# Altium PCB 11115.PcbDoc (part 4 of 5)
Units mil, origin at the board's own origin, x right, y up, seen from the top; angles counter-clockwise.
Board outline 4800 x 3500.1 mil, 4 copper layers (Top Layer, Layer 2, Layer 3, Bottom Layer), stack 61.6 mil thick; 316 components, 224 nets, 954 pads, 623 vias.
Unrouted connection lines stored in the file: 268.
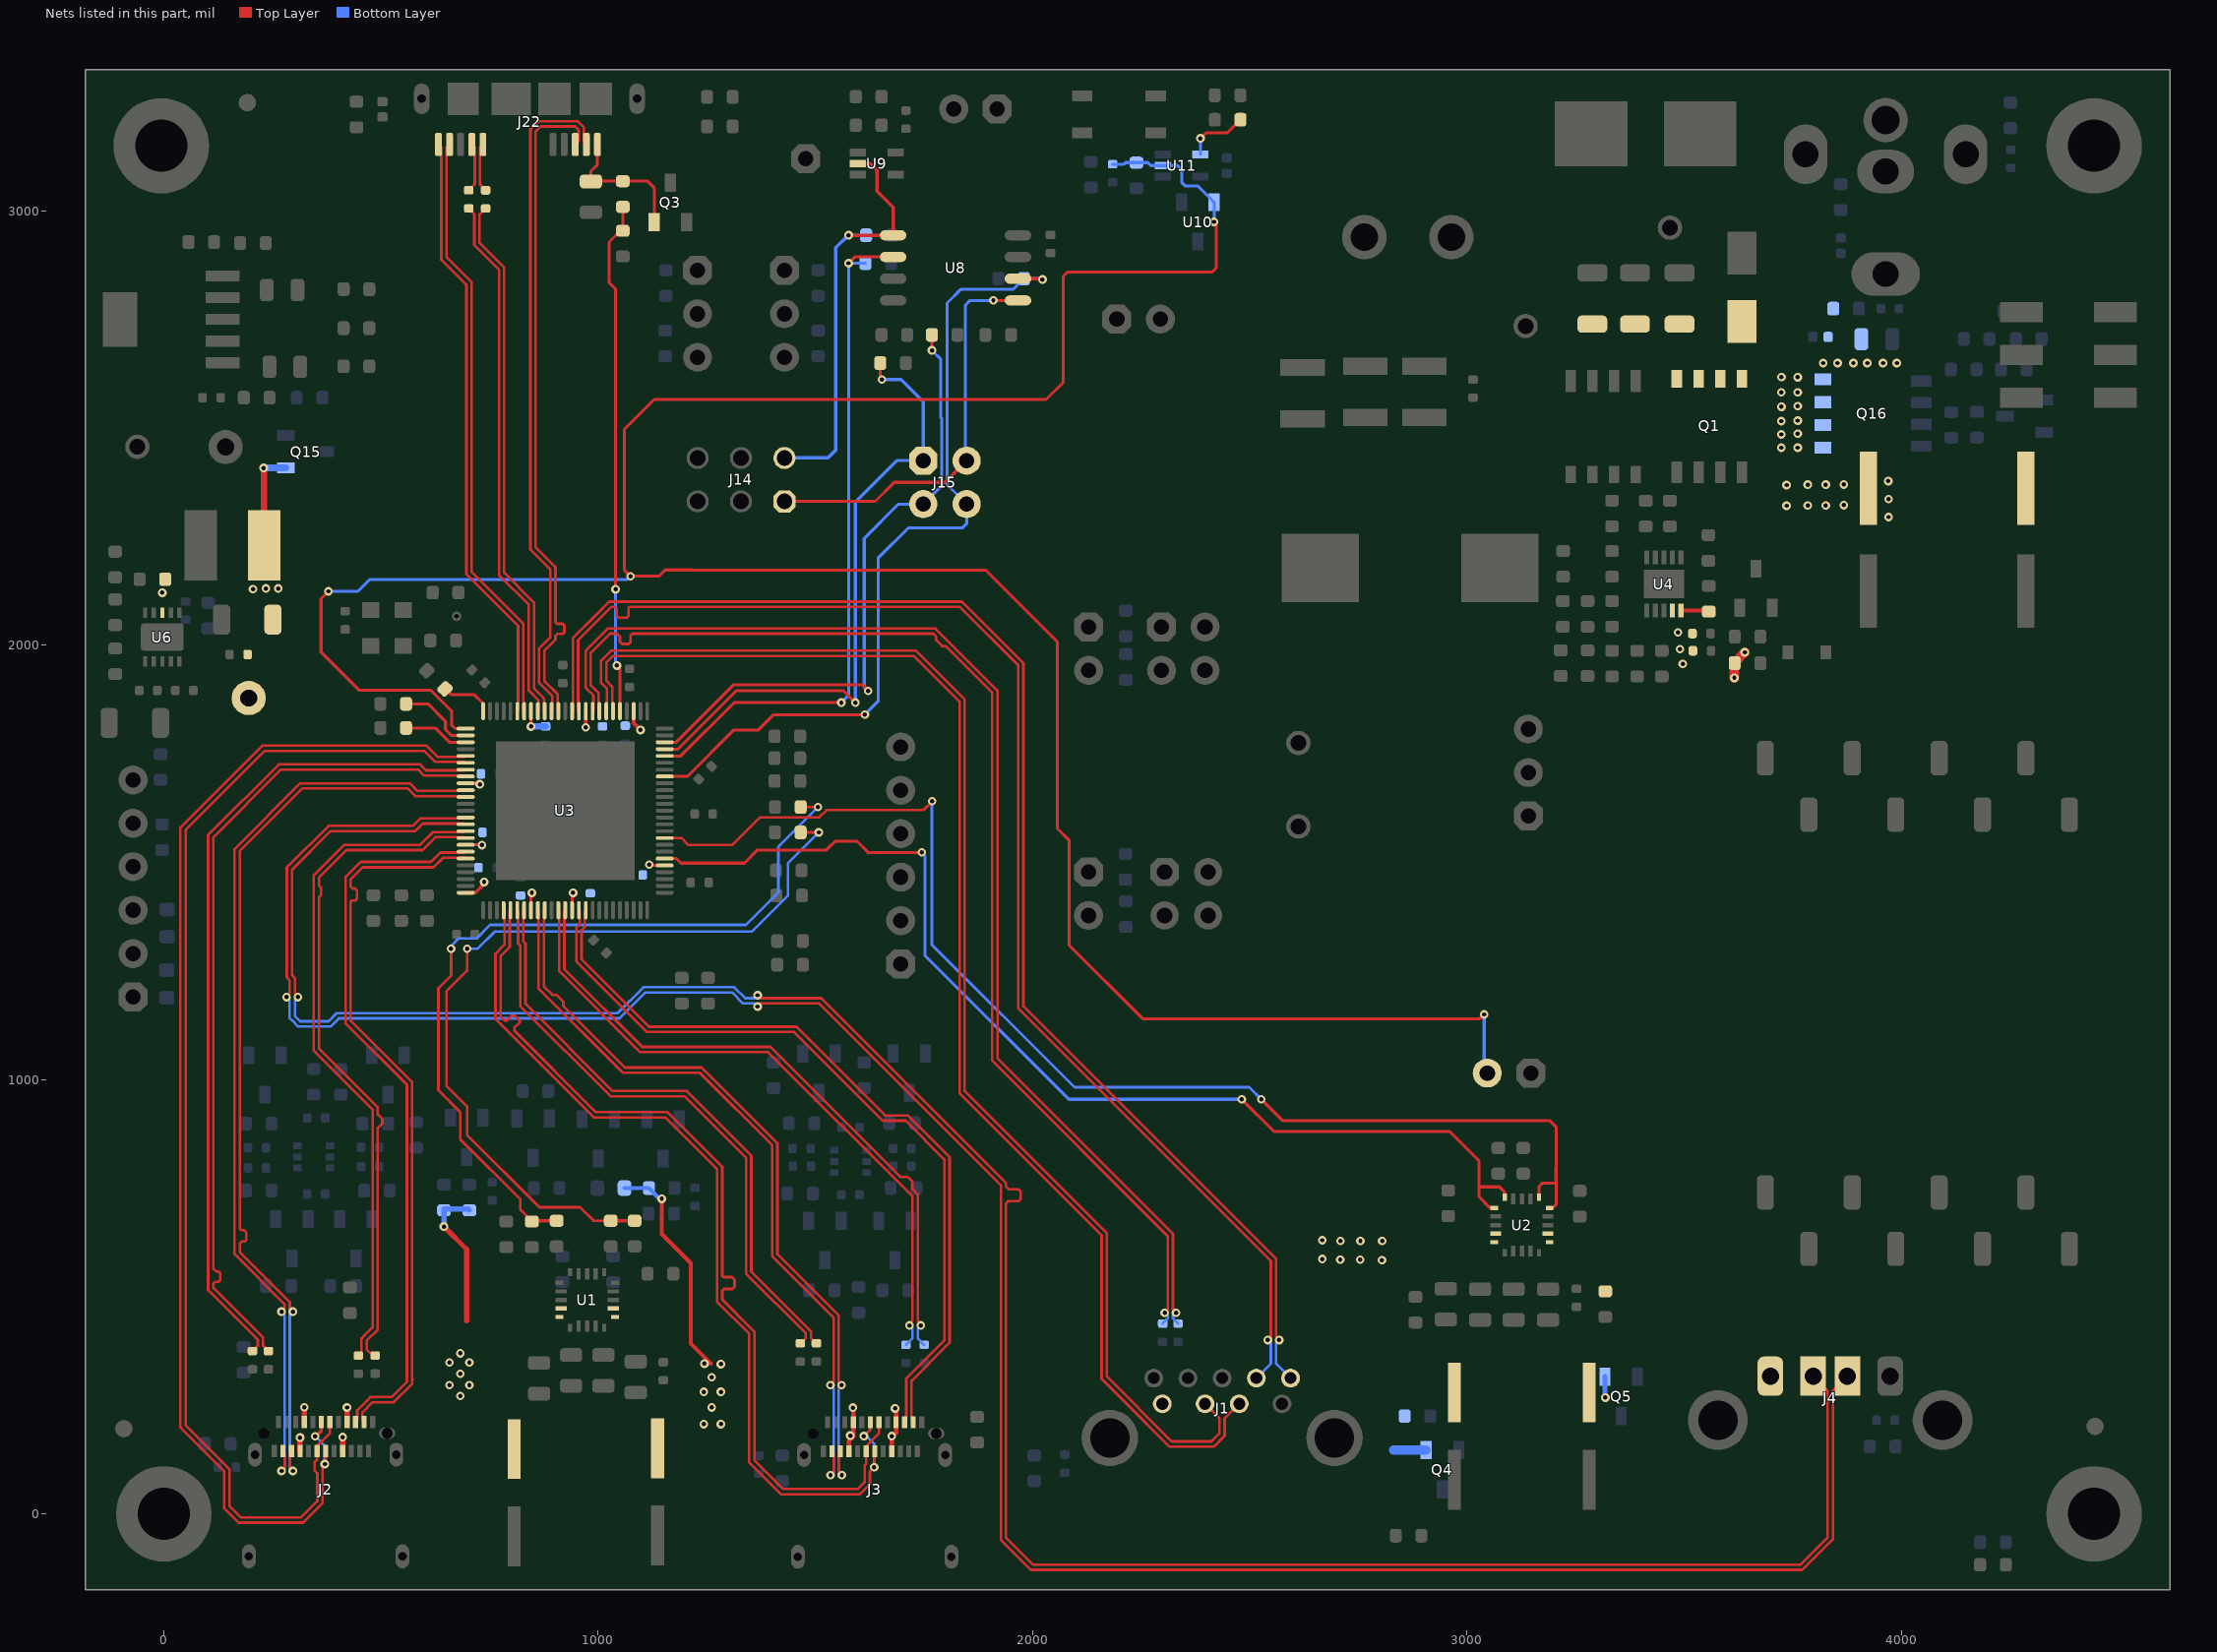
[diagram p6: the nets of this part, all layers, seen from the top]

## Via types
v1: diameter 20, hole 10, Top Layer to Bottom Layer, tented both sides, 576 vias
v2: diameter 23, hole 11, Top Layer to Bottom Layer, 36 vias
v3: diameter 20, hole 12, Top Layer to Bottom Layer, 7 vias
v4: diameter 27.56, hole 11.81, Top Layer to Bottom Layer, 4 vias

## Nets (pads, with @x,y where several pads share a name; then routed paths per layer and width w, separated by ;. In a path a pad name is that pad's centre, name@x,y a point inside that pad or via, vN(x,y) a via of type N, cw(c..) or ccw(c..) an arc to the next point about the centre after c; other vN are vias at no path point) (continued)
PF30: R30.2 U3.2 | length 178.5
  Top Layer w7: R30.2@557.83,1865 608.51,1865 648.65,1824.86 648.65,1805.68 661.96,1792.36 U3.2@695.05,1792.36
PF31: R28.2 U3.3 | length 150.9
  Top Layer w7: R28.2@557.83,1809.63 624.5,1809.63 657.51,1776.61 U3.3@695.05,1776.61
PG5V: R53.1 U4.5 | length 65
  Top Layer w10: U4.5@3493.07,2080.03 3554.54,2080.03 R53.1@3557.07,2077.51
PRT_CTL1: R7.1 R8.1 R25.1 | length 1872
  Top Layer w6: v1(661.52,1301.28) 661.52,1239.71 632.15,1210.34 632.15,975.51 682.61,925.06 682.61,862.65 820.82,724.43 820.82,700 R7.1@847.44,673.39 ; R25.1@1466.32,1627.49 v1(1506.19,1627.49)
  Top Layer w8: R7.1@847.44,673.39 848.91,674.86 R8.1@904.51,674.86
  Bottom Layer w6: v1(661.52,1301.28) 661.52,1307.61 678.91,1325 720.29,1325 751.27,1355.98 1339.99,1355.98 1414.93,1430.92 1414.93,1536.23 v1(1506.19,1627.49)
PRT_CTL2: R9.2 R10.2 R24.1 | length 1942
  Top Layer w6: v1(698.37,1301.28) 698.37,1255.7 698.07,1255.39 698.07,1250.64 650.56,1203.13 650.56,985.92 698.37,938.11 698.37,872.48 864.99,705.86 958.56,705.86 989.56,674.86 R9.2@1029.08,674.86 ; R24.1@1466.32,1569.14 v1(1508.16,1569.14)
  Top Layer w8: R9.2@1029.08,674.86 R10.2@1083.89,674.86
  Bottom Layer w6: v1(698.37,1301.28) 722.52,1301.28 761.91,1340.67 1354.1,1340.67 1436.79,1423.35 1436.79,1497.78 v1(1508.16,1569.14)
PRT_CTL3: U2.1 U2.20 U3.56 | length 2544
  Top Layer w6: 3062.11,753.02 3062.67,753.58 3063.23,753.02
  Top Layer w7: U3.56@1153.32,1508.9 1179.97,1508.9 1190.64,1498.23 1336.75,1498.23 1367.07,1528.55 1525.59,1528.55 1545.56,1548.52 1596.04,1548.52 1621.53,1523.03 v1(1744.91,1523.03) ; v1(2481.65,954.65) 2555.98,880.31 2960.71,880.31 3028.02,813.01 3028.02,753.02 ; 3062.11,753.02 3028.02,753.02 ; U2.1@3062.67,704.37 3053.61,704.37 3028.02,729.96 3028.02,753.02 ; 3063.23,753.02 3075.05,753.02 3087.28,740.79 U2.20@3087.28,728.98
  Bottom Layer w7: v1(1744.91,1523.03) 1752.25,1515.7 1752.25,1286.09 2083.68,954.65 v1(2481.65,954.65)
PRT_CTL4: U2.15 U2.16 U3.59 | length 2869.9
  Top Layer w6: U3.59@1153.32,1556.14 1191.68,1556.14 1207.82,1540 1308.9,1540 1372.64,1603.74 1509.31,1603.74 1526.03,1620.46 1748.52,1620.46 v1(1769.05,1640.99)
  Top Layer w7: v1(2526.65,954.65) 2575.56,905.73 3190.62,905.73 3205.39,890.97 3205.39,798.2 3205.16,797.97 3205.16,760.83 ; U2.16@3166.02,728.98 3166.02,753.58 3173.49,761.05 3204.94,761.05 3205.39,760.6 3205.39,712.25 3197.51,704.37 U2.15@3190.62,704.37
  Bottom Layer w7: v1(1769.05,1640.99) 1768.11,1640.05 1768.11,1310.79 2096.65,982.25 2499.05,982.25 v1(2526.65,954.65)
RBIAS: R31.2 U3.100 | length 115.7
  Top Layer w7: R31.2@650.27,1897.76 662.2,1885.83 715.18,1885.83 735.21,1865.8 U3.100@735.21,1848.27
RST: R60.1 U11.4 | length 146.8
  Top Layer w7: v1(2386.67,3167.01) 2399.62,3179.95 2448.63,3179.95 R60.1@2478.68,3210
  Bottom Layer w7: U11.4@2386.67,3130 v1(2386.67,3167.01)
RST_N: C101.2 J6.2 R120.1 U3.1 U10.2 U11.2 | length 6663.8
  Top Layer w7: v1(379.19,2124.18) 362,2107 362,1984.2 450.15,1896.05 615.04,1896.05 662.37,1848.72 662.37,1816.5 670.76,1808.11 U3.1@695.05,1808.11 ; v1(2417.51,2974.72) 2422.89,2969.34 2422.89,2868.79 2413.84,2859.73 2081.04,2859.73 2070.61,2849.3 2070.61,2605.17 2031.26,2565.82 1129.17,2565.82 1060.06,2496.71 1060.06,2173.29 v1(1074.51,2158.84) 1139.75,2158.84 1154.31,2173.4 1216.03,2173.4 1216.93,2172.49 1892.92,2172.49 2057.06,2008.35 2057.06,1578.3 2084.15,1551.21 2084.15,1309.83 2253.98,1140 3029.8,1140 v1(3039.8,1150)
  Bottom Layer w7: v1(379.19,2124.18) 446.63,2124.18 473.82,2151.38 1067.05,2151.38 v1(1074.51,2158.84) ; C101.2@2184.47,3107.56 2210.65,3107.56 2214.35,3111.25 R120.1@2239.15,3111.25 2265.66,3111.25 2272.5,3104.41 U11.2@2300.06,3104.41 2333.53,3104.41 2343.37,3094.58 2343.37,3065.98 2352.18,3057.17 2381,3057.17 U10.2@2418.17,3020 2418.17,2975.38 v1(2417.51,2974.72) ; v1(3039.8,1150) 3039.8,1022.22 J6.2@3047.02,1015
SPI_CE/PF20: J14.4 R118.1 U8.1 U9.2 | length 990.7
  Top Layer w8: v1(1576.65,2943.98) U8.1@1679.05,2943.98 1679.05,3008.28 1641.65,3045.69 1641.65,3093.88 1626.39,3109.13 U9.2@1598.34,3109.13
  Bottom Layer w8: J14.4@1428.96,2431.29 1429.06,2431.39 1529.25,2431.39 1547,2449.15 1547,2915.09 1575.9,2943.98 v1(1576.65,2943.98) R118.1@1616.95,2943.98
SPI_CLK/PF21: J15.4 R115.2 U3.68 U8.6 | length 1957.3
  Top Layer w7: U3.68@1153.32,1697.87 1153.65,1698.21 1179.74,1698.21 1205.58,1698.23 1312.35,1805 1369.15,1805 1404.34,1840.2 v1(1613.99,1840.2) ; U8.6@1966.45,2843.98 2021.09,2843.98 v1(2023.09,2841.98)
  Bottom Layer w7: v1(1613.99,1840.2) 1644.64,1870.85 1644.64,2200.83 1713.81,2270 1838.12,2270 1849,2280.88 1848.52,2281.37 J15.4@1848.52,2325 1803.61,2369.91 1803.61,2787.95 1834.84,2819.18 1955.3,2819.18 R115.2@1980.11,2843.98 2021.09,2843.98 v1(2023.09,2841.98)
SPI_D2/PF24: J15.1 R49.2 U3.72 | length 1455.4
  Top Layer w7: U3.72@1153.32,1760.87 1183.76,1760.87 1318.54,1895.65 1564.4,1895.65 v1(1592.28,1867.77) ; R49.2@1649.52,2649.73 1649.52,2615.82 v1(1653.49,2611.85)
  Bottom Layer w7: v1(1592.28,1867.77) 1592.28,2329.76 1687.52,2425 J15.1@1748.52,2425 1748.52,2560.61 1697.27,2611.85 v1(1653.49,2611.85)
SPI_D3/PF25: J15.3 R51.2 U3.73 | length 1461.2
  Top Layer w7: U3.73@1153.32,1776.61 1179.53,1776.61 1311.56,1908.65 1609.83,1908.65 v1@1616.79,1901.69 ; v1(1768.44,2678.98) R51.2@1768.44,2714.67
  Bottom Layer w7: v1(1621.53,1894.61) 1612.48,1903.66 1612.48,2246.06 1691.42,2325 J15.3@1748.52,2325 1790.52,2367 1790.52,2522.88 1789.15,2524.24 1789.15,2658.28 v1(1768.44,2678.98)
SPI_MISO/PF23: R117.2 U3.71 U8.2 | length 1623
  Top Layer w7: U3.71@1153.32,1745.12 1190.22,1745.12 1312.87,1867.77 v1(1559.89,1867.77) ; v1(1576.65,2879.73) 1590.9,2893.98 U8.2@1679.05,2893.98
  Bottom Layer w7: v1(1559.89,1867.77) 1576.65,1884.53 v1(1576.65,2879.73) R117.2@1615.11,2879.73
SPI_MOSI/PF22: J14.1 J15.2 U8.5 | length 950.8
  Top Layer w7: J14.1@1428.96,2331.29 1638.03,2331.29 1681.74,2375 1798.52,2375 J15.2@1848.52,2425 ; v1(1909.92,2793.98) U8.5@1966.45,2793.98 1971.58,2793.98 U8.5@1973.41,2792.15
  Bottom Layer w7: J15.2@1848.52,2425 1845.61,2427.91 1845.61,2783.22 1856.37,2793.98 v1(1909.92,2793.98)
UP_N: C57.1 J22.7 | length 113.9
  Top Layer w6: C57.1@702,3047.65 715.9,3061.54 715.9,3146.22 J22.7@709.1,3153.02
UP_P: C58.1 J22.6 | length 113.7
  Top Layer w6: J22.6@734.69,3153.02 727.9,3146.22 727.9,3060.61 C58.1@741,3047.51
USB2DN1/PRT_DIS_1_N: J2.A7 J2.B7 U3.6 | length 2758.4
  Top Layer w6: J2.A7@382.49,211.58 382.49,185.83 352.96,156.3 J2.B7@352.96,144.65 352.96,125.14 347,119.18 347,100.29 353.65,93.64 353.65,29.73 315.91,-8 177.38,-8 151.15,18.23 151.15,103.15 130.94,123.36 50.23,204.07 50.23,1574.97 232.13,1756.87 599.57,1756.87 625.19,1731.24 693.17,1731.24 U3.6@695.05,1729.37
USB2DN1/PRT_DIS_1_P: J2.A6 J2.B6 U3.5 | length 2877.7
  Top Layer w6: v1(348.52,178.73) 362.8,193.01 ; 357.08,184.17 362.8,189.89 362.8,193.01 ; J2.A6@362.8,211.58 362.8,193.01 ; v1@362.89,111.73 v1@365.89,114.73 ; J2.B6@372.65,144.65 372.65,121.49 v1@365.89,114.73 ; U3.5@695.05,1745.12 693.17,1743.24 630.16,1743.24 604.54,1768.87 227.16,1768.87 38.23,1579.94 38.23,199.1 46.96,190.36 139.15,98.17 139.15,13.26 172.41,-20 320.88,-20 365.65,24.76 365.65,109.73 v1(370.65,114.73) v1@365.89,114.73
  Bottom Layer w6: v1(348.52,178.73) 370.65,156.61 v1(370.65,114.73) v1@365.65,109.73
USB2DN2/PRT_DIS_2_N: J3.A7 J3.B7 U3.30 | length 2139.1
  Top Layer w6: U3.30@798.2,1390 796.32,1388.13 796.32,1305.52 775.64,1284.83 775.64,1144.52 783.89,1136.26 790.32,1136.26 801.06,1147 808.26,1147 819,1136.26 819,1131 807,1119 807,1113.16 995.1,925.06 1159.65,925.06 1285.65,799.07 1285.65,547.96 1288.59,545.02 1308.12,545.02 1314,539.15 1314,523 1309,518 1290,518 1285.65,513.65 1285.65,493.56 1359.61,419.6 1359.61,123.5 1425.93,57.18 1597.59,57.18 1613.65,73.23 1613.65,111.23 1616.65,114.23 1616.65,115.1 1616.96,115.42 J3.B7@1616.96,144 1616.96,155.32 1646.49,184.84 J3.A7@1646.49,210.93
USB2DN2/PRT_DIS_2_P: J3.A6 J3.B6 U3.29 | length 2140.6
  Top Layer w6: U3.29@782.45,1390 784.32,1388.13 784.32,1310.49 763.64,1289.8 763.64,1139.55 990.13,913.06 1154.68,913.06 1273.65,794.1 1273.65,488.59 1347.61,414.63 1347.61,118.53 1420.96,45.18 1602.56,45.18 1606.08,48.7 1625.65,68.26 1625.65,97.23 v1(1635.65,107.23) 1636.65,108.23 J3.B6@1636.65,144 ; v1(1611.65,179.08) 1626.8,194.23 J3.A6@1626.8,210.93
  Bottom Layer w6: v1(1611.65,179.08) 1617.21,179.08 1635.65,160.64 v1(1635.65,107.23)
USB2DN3/PRT_DIS_3_N: J1.2 U3.82 | length 3121.3
  Top Layer w6: U3.82@1018.67,1848.27 1020.54,1850.14 1020.54,1899.73 1006.67,1913.6 1006.67,1964.45 1029.68,1987.46 1731.82,1987.46 1844,1875.29 1844,973.21 1964.15,853.06 2171.15,646.06 2171.15,316.16 2320.49,166.82 2412.17,166.82 2430.13,184.78 2430.13,220.62 J1.2@2397.28,253.47
USB2DN3/PRT_DIS_3_P: J1.3 U3.81 | length 3121.7
  Top Layer w6: U3.81@1034.42,1848.27 1032.54,1850.14 1032.54,1904.7 1018.67,1918.57 1018.67,1959.48 1034.65,1975.46 1726.85,1975.46 1832,1870.32 1832,968.24 2159.15,641.09 2159.15,311.19 2214.65,255.7 2315.52,154.82 2417.14,154.82 2442.13,179.81 2442.13,219.59 J1.3@2476.02,253.47
USB2DN4/PRT_DIS_4_N: J4.2 U3.15 | length 5857.2
  Top Layer w6: v1(308.94,1190) 301.94,1197 301.94,1233.62 295.2,1240.36 295.2,1483.19 384.16,1572.14 578.76,1572.14 587.61,1580.99 596.13,1589.51 693.17,1589.51 U3.15@695.05,1587.64 ; v1(1367.07,1194.21) 1374.07,1187.21 1513.8,1187.21 1896.15,804.85 1939.15,761.85 1939.15,753.85 1946,747 1968,747 1973,742 1973,725 1968,720 1944,720 1939.15,715.15 1939.15,-55 2001.15,-117 3767.22,-117 3830.65,-53.57 3830.65,283.61 J4.2@3797.28,316.98
  Bottom Layer w6: v1(308.94,1190) 301.94,1183 301.94,1146.33 314.31,1133.96 379.32,1133.96 398.18,1152.82 1044.54,1152.82 1104.28,1212.57 1313.17,1212.57 1338.53,1187.21 1360.07,1187.21 v1(1367.07,1194.21)
USB2DN4/PRT_DIS_4_P: J4.3 U3.14 | length 5859.9
  Top Layer w6: v1@275,1190 v1(282.94,1190) ; v1@289.94,1197 289.94,1228.65 283.2,1235.39 283.2,1488.16 379.19,1584.14 573.79,1584.14 591.16,1601.51 693.17,1601.51 U3.14@695.05,1603.39 ; v1(1367.07,1168.21) 1374.07,1175.21 1508.83,1175.21 1927.15,756.88 1927.15,-59.97 1996.18,-129 3772.19,-129 3802.67,-98.52 3842.65,-58.54 3842.65,283.61 J4.3@3876.02,316.98
  Bottom Layer w6: v1(282.94,1190) 289.94,1183 289.94,1141.36 295.26,1136.03 309.34,1121.96 384.29,1121.96 403.16,1140.82 1049.51,1140.82 1109.25,1200.57 1308.2,1200.57 1333.56,1175.21 1360.07,1175.21 v1(1367.07,1168.21)
USB2UP_N: J22.2 U3.90 | length 1565.5
  Top Layer w6: U3.90@892.69,1848.27 894.56,1850.14 894.56,1882.97 864.23,1913.29 864.23,1992.56 889.66,2017.99 889.66,2174.99 844.15,2220.5 844.15,3187.84 861.6,3205.29 862.99,3206.68 952.42,3206.68 967,3192.1 967,3158.9 J22.2@972.88,3153.02 J22.2@972.88,3148.02
USB2UP_P: J22.3 U3.89 | length 1566
  Top Layer w6: U3.89@908.43,1848.27 906.56,1850.14 906.56,1887.94 876.23,1918.26 876.23,1987.59 901.66,2013.02 901.66,2021.5 906.68,2026.52 919.06,2026.52 922.31,2029.77 922.31,2045.68 918.59,2049.4 905.6,2049.4 901.66,2053.34 901.66,2179.96 856.15,2225.47 856.15,3182.87 867.96,3194.68 947.45,3194.68 955,3187.13 955,3160.72 J22.3@947.29,3153.02 J22.3@947.29,3148.02 ; J22.3@948.65,3146.65 J22.3@947.29,3148.02 ; J22.3@948.65,3153.02 948.65,3149.38 J22.3@947.29,3148.02
USB3DN_RX1A_N: J2.B10 U3.11 | length 2141.8
  Top Layer w6: J2.B10@293.91,144.65 290.06,140.81 290.06,105.76 v1(297.06,98.76) ; v1(297.06,465.65) 290.06,472.65 290.06,487.78 174.9,602.94 174.9,622.38 179.52,627 186,627 190,631 190,648 185,653 179,653 174.9,657.1 174.9,1526.11 318.93,1670.13 561.45,1670.13 579.08,1652.5 693.17,1652.5 U3.11@695.05,1650.63
  Bottom Layer w6: v1(297.06,98.76) 290.06,105.76 290.06,458.65 v1(297.06,465.65)
USB3DN_RX1A_P: J2.B11 U3.10 | length 2141.9
  Top Layer w6: v1(271.06,98.76) 278.06,105.76 278.06,140.81 J2.B11@274.22,144.65 ; v1(271.06,465.65) 278.06,472.65 278.06,482.81 162.9,597.97 162.9,1531.08 313.96,1682.13 566.42,1682.13 584.05,1664.5 693.17,1664.5 U3.10@695.05,1666.38
  Bottom Layer w6: v1(271.06,98.76) 278.06,105.76 278.06,458.65 v1(271.06,465.65)
USB3DN_RX1B_N: J2.A10 U3.19 | length 1691.5
  Top Layer w6: J2.A10@441.54,211.58 445.39,215.43 445.39,238.47 475.83,268.91 524.41,268.91 559.75,304.25 559.75,988.59 418.34,1130 418.34,1466.21 452.73,1500.61 452.84,1500.61 453.22,1500.99 614.95,1500.99 636.73,1522.77 693.17,1522.77 U3.19@695.05,1524.65
USB3DN_RX1B_P: J2.A11 U3.20 | length 1691.8
  Top Layer w6: J2.A11@461.23,211.58 457.39,215.43 457.39,233.5 480.8,256.91 529.38,256.91 571.75,299.28 571.75,993.56 430.34,1134.97 430.34,1409.34 433,1412 441,1412 445,1416 445,1435 440,1440 434.34,1440 430.34,1444 430.34,1461.24 457.7,1488.61 620.98,1488.61 643.15,1510.77 693.17,1510.77 U3.20@695.05,1508.9
USB3DN_RX2A_N: J3.B10 U3.35 | length 1757.1
  Top Layer w6: U3.35@876.94,1390 875.06,1388.13 875.06,1214.36 894.56,1194.86 904.45,1194.86 919.94,1179.37 919.94,1169.48 1061.66,1027.76 1238.44,1027.76 1412.81,853.39 1412.81,598.03 1554.06,456.78 v1@1554.06,289.85 ; v1@1554.06,92.85 1554.06,140.16 J3.B10@1557.91,144
  Bottom Layer w6: v1(1560.65,296.43) 1554.06,289.85 1554.06,96.27 v1(1561.06,89.27)
USB3DN_RX2A_P: J3.B11 U3.34 | length 1756.6
  Top Layer w6: U3.34@861.19,1390 863.06,1388.13 863.06,1209.39 1056.69,1015.76 1233.47,1015.76 1400.81,848.42 1400.81,593.06 1446.1,547.77 1542.06,451.81 1542.06,304.72 1541.65,304.3 1541.65,303.43 v1(1534.65,296.43) ; v1(1535.06,89.27) 1538.48,89.27 1542.06,92.85 1542.06,140.16 J3.B11@1538.22,144
  Bottom Layer w6: v1(1534.65,296.43) 1541.65,289.43 1541.65,288.56 1542.06,288.14 1542.06,96.27 v1(1535.06,89.27)
USB3DN_RX2B_N: J3.A10 U3.40 | length 1801.3
  Top Layer w6: U3.40@955.68,1390 957.55,1388.13 957.55,1356.63 949.82,1348.9 949.82,1271.87 1112.14,1109.55 1451.43,1109.55 1655.54,905.44 1707.91,905.44 1797,816.35 1797,399.23 1709.39,311.61 1709.39,225.23 1708.45,224.29 1708.45,213.84 J3.A10@1705.54,210.93
USB3DN_RX2B_P: J3.A11 U3.41 | length 1801.3
  Top Layer w6: U3.41@971.43,1390 969.55,1388.13 969.55,1351.66 961.82,1343.93 961.82,1276.84 1117.11,1121.55 1456.4,1121.55 1660.51,917.44 1712.88,917.44 1809,821.32 1809,394.26 1721.39,306.64 1721.39,225.23 1722.32,224.29 1722.32,213.84 J3.A11@1725.23,210.93
USB3DN_RX3_N: J1.5 U3.87 | length 3206.5
  Top Layer w6: U3.87@939.93,1848.27 941.8,1850.14 941.8,2016.82 997.5,2072.52 1025.23,2100.25 1837.52,2100.25 1979.15,1958.62 1979.15,1168.9 2560.76,587.29 2560.76,407.25 v1(2567.76,400.25)
  Bottom Layer w6: v1(2567.76,400.25) 2560.76,393.25 2560.76,345.9 J1.5@2594.13,312.53
USB3DN_RX3_P: J1.6 U3.86 | length 3206.4
  Top Layer w6: U3.86@955.68,1848.27 953.8,1850.14 953.8,2011.85 1030.2,2088.25 1037.75,2088.25 1043.1,2082.9 1043.1,2067.64 1047.03,2063.71 1065.93,2063.71 1070.06,2067.84 1070.06,2085.5 1072.8,2088.25 1832.55,2088.25 1967.15,1953.65 1967.15,1163.93 2548.76,582.32 2548.76,407.25 v1(2541.76,400.25)
  Bottom Layer w6: J1.6@2515.39,312.53 2548.76,345.9 2548.76,393.25 v1(2541.76,400.25)
USB3DN_TX1A_N: C10.1 U3.8 | length 1908
  Top Layer w6: C10.1@241.01,374.84 228.65,387.21 228.65,405.74 114.23,520.15 114.23,530.23 118.61,534.61 125.98,534.61 130,538.63 130,554 126.23,557.77 120.85,557.77 114.23,564.39 114.23,1557.97 269.88,1713.62 585.38,1713.62 599.26,1699.75 693.17,1699.75 U3.8@695.05,1697.87
USB3DN_TX1A_P: C9.1 U3.7 | length 1907.4
  Top Layer w6: C9.1@204.2,374.84 216.65,387.29 216.65,400.76 211.65,405.76 162.91,454.51 102.23,515.18 102.23,1562.94 264.91,1725.62 590.35,1725.62 604.23,1711.75 693.17,1711.75 U3.7@695.05,1713.62
USB3DN_TX1B_N: C11.1 U3.16 | length 1567.2
  Top Layer w6: C11.1@447.94,364.31 455,371.37 455,403.66 461.23,409.88 480.65,429.3 480.65,931.27 348.9,1063.02 345.39,1066.53 345.39,1470.04 415.74,1540.39 590.67,1540.39 620.29,1570.02 693.17,1570.02 U3.16@695.05,1571.89
USB3DN_TX1B_P: C12.1 U3.17 | length 1567.6
  Top Layer w6: C12.1@486.52,364.68 481.23,364.68 467,378.91 467,398.69 492.65,424.33 492.65,888.65 503,899 503,909.77 492.65,920.13 492.65,936.24 357.39,1071.5 357.39,1420 362,1424.61 362,1442.38 357.39,1446.99 357.39,1465.06 420.71,1528.39 595.64,1528.39 611.59,1544.34 625.26,1558.02 693.17,1558.02 U3.17@695.05,1556.14
USB3DN_TX2A_N: C15.1 U3.32 | length 1377.4
  Top Layer w6: U3.32@829.69,1390 827.82,1388.13 827.82,1318.1 832.55,1313.37 832.55,1174.71 1033.6,973.67 1203.99,973.67 1352.65,825.01 1352.65,557.77 1489.95,420.46 1489.95,405.08 C15.1@1502.38,392.65
USB3DN_TX2A_P: C14.1 U3.31 | length 1377.4
  Top Layer w6: U3.31@813.95,1390 815.82,1388.13 815.82,1313.13 820.55,1308.4 820.55,1169.74 1028.63,961.67 1199.02,961.67 1340.65,820.04 1340.65,552.8 1477.95,415.49 1477.95,405.08 C14.1@1465.53,392.65
USB3DN_TX2B_N: C67.1 U3.37 | length 1523.4
  Top Layer w6: U3.37@908.43,1390 910.31,1388.13 910.31,1249.68 1096.74,1063.25 1391.28,1063.25 1723.69,730.85 1723.69,444.41 1716.69,437.41 v1(1716.69,433.89)
  Bottom Layer w6: C67.1@1708.65,389.1 1723.69,404.14 1723.69,427.23 1717.02,433.89 v1(1716.69,433.89)
USB3DN_TX2B_P: C66.1 U3.38 | length 1523.4
  Top Layer w6: U3.38@924.18,1390 922.31,1388.13 922.31,1254.66 1101.71,1075.25 1396.25,1075.25 1695.75,775.75 1712.79,775.75 1723.69,764.86 1723.69,747.82 1735.69,735.82 1735.69,444.41 1742.69,437.41 v1(1742.69,433.89)
  Bottom Layer w6: v1@1735.69,427.23 1735.69,404.27 C66.1@1750.73,389.23
USB3DN_TX3_N: C68.1 U3.84 | length 2811.5
  Top Layer w6: U3.84@987.17,1848.27 989.05,1850.14 989.05,1884.76 974.64,1899.17 971.13,1902.68 971.13,1987.46 974.64,1990.98 1010.19,2026.52 1022.25,2038.58 1776.42,2038.58 1919.15,1895.85 1919.15,1048.98 2323.44,644.68 2323.44,470 v1(2330.44,463)
  Bottom Layer w6: v1(2330.44,463) 2323.44,456 2323.44,449.95 C68.1@2335.17,438.22
USB3DN_TX3_P: C69.1 U3.83 | length 2811.9
  Top Layer w6: U3.83@1002.92,1848.27 1001.05,1850.14 1001.05,1889.73 983.13,1907.65 983.13,1982.49 1027.22,2026.58 1043.92,2026.58 1050.17,2020.34 1050.17,2007.83 1055,2003 1070.06,2003 1074.51,2007.45 1074.51,2022.09 1079,2026.58 1771.45,2026.58 1778,2020.03 1778,2011.83 1791.82,1998.01 1800.01,1998.01 1907.15,1890.88 1907.15,1044.01 2311.44,639.71 2311.44,470 v1(2304.44,463)
  Bottom Layer w6: C69.1@2299.72,438.23 2311.44,449.95 2311.44,456 v1(2304.44,463)
USB3UP_RX_N: J22.9 U3.94 | length 1381.5
  Top Layer w6: J22.9@657.92,3153.02 651.13,3146.22 651.13,2892.87 708.68,2835.32 708.68,2168.54 827.82,2049.4 827.82,1850.14 U3.94@829.69,1848.27
USB3UP_RX_P: J22.10 U3.95 | length 1381.5
  Top Layer w6: J22.10@632.33,3153.02 639.13,3146.22 639.13,2887.9 696.68,2830.35 696.68,2163.57 815.82,2044.43 815.82,1850.14 U3.95@813.95,1848.27
USB3UP_TX_N: C57.2 U3.92 | length 1225.1
  Top Layer w6: C57.2@702,3005.91 715,2992.91 715,2921.37 771.73,2864.65 771.73,2161.81 840.23,2093.3 840.23,1895.88 863.06,1873.05 863.06,1850.14 U3.92@861.19,1848.27
USB3UP_TX_P: C58.2 U3.91 | length 1225.4
  Top Layer w6: C58.2@741,3005.78 727,2991.78 727,2926.34 783.73,2869.62 783.73,2166.78 852.23,2098.27 852.23,1900.85 875.06,1878.02 875.06,1850.14 U3.91@876.94,1848.27
VBUS1: C1.1 J2.A4 J2.A9 J2.B4 J2.B9 R76.2 R77.2 U1.4 U1.5 | length 473.5
  Top Layer w12: J2.B9@313.59,144.65 v1(313.59,175.68) v1@316.65,178.73 ; J2.A4@323.43,211.58 v1@323.43,245.07 ; J2.B4@412.02,144.65 v1(412.02,176.86) ; J2.A9@421.86,211.58 v1(421.86,244.85) ; v1(644.91,661.68) 697.38,609.21 697.38,444.13
  Bottom Layer w12: v1(644.91,661.68) R77.2@644.91,699.04 644.91,701.7 700.97,701.7 R76.2@703.65,699.02
  other v1: 323.43,245.65 682.55,271.62 657.65,296.43 703.65,296.43 682.55,322.54 657.65,348.56 703.65,348.56 682.55,369.86
VBUS2: C2.1 J3.A4 J3.A9 J3.B4 J3.B9 R80.2 R81.2 U1.11 U1.12 | length 731.2
  Top Layer w10: v1(1146.38,725.36) 1146.38,644.02 1213.22,577.18 1213.22,392.35 1259.67,345.91 ; J3.B9@1577.59,144 1577.59,168.18 1587.43,178.02 J3.A4@1587.43,210.93 v1@1587.43,244.73 ; J3.B4@1676.02,144 1676.02,176.22 1685.86,186.07 J3.A9@1685.86,210.93 1685.86,240.57 v1(1683.65,242.79) v1@1683.65,242.55
  Bottom Layer w10: R81.2@1060.69,750.16 R80.2@1116.86,750.16 1141.66,725.36 v1(1146.38,725.36)
  other v1: 1676.02,179.08 1580.65,180.23 1243.22,206.77 1282.65,206.77 1261.56,245.07 1586.65,244.73 1243.22,281.03 1282.65,281.03 1261.56,314.42 1282.65,344.85 1244.67,345.91
VBUS3: C3.1 J1.1 Q4.1 R66.2 U2.4 U2.5 | length 75.4
  Bottom Layer w22: 2831.09,147.06 Q4.1@2906.45,147.06
  other v1: 2804.59,584.22 2708.42,585.46 2754.44,585.16 2667.14,586.72 2708.92,628.39 2754.93,628.39 2805.09,628.39 2667.14,630.08
VBUS4: C4.1 J4.1 Q5.1 R4.2 U2.11 U2.12 | length 48.1
  Bottom Layer w12: Q5.1@3317.99,315.73 3317.99,268.69 v1(3318.76,267.92)
VBUS_0: C59.2 J22.1 Q3.1 R56.1 | length 318.3
  Top Layer w7: J22.1@998.47,3148.02 998.47,3106.76 983.29,3091.58 C59.2@983.29,3067.79 983.94,3068.44 R56.1@1056.65,3068.44 1114.07,3068.44 1129.24,3053.26 Q3.1@1129.17,2974.04 Q3.1@1129.17,2974.04
VBUS_DET: R54.2 R56.2 U3.80 | length 1189.9
  Top Layer w7: v1(1040.31,2128.81) 1040.31,2819.77 1025.23,2834.85 1025.23,2928.32 R54.2@1056.65,2959.73 ; v1(1043.1,1953.37) 1050.17,1946.3 U3.80@1050.17,1848.27 ; R54.2@1056.65,2954.26 R54.2@1056.65,2959.73 ; R56.2@1056.65,3009.38 R54.2@1056.65,2959.73
  Bottom Layer w7: v1(1040.31,2128.81) 1040.31,1956.16 v1(1043.1,1953.37)
VCORE: C26.2 C84.1 C85.1 C86.1 C87.1 C88.1 C89.1 C90.1 C91.1 C92.1 C97.2 L2.2 Q15.1 R112.2 TP5.1 U3.9 U3.18 U3.25 U3.33 U3.39 U3.55 U3.78 U3.85 U3.93 U6.3 | length 654.7
  Top Layer w7: U3.25@677.61,1430.16 U3.25@695.05,1430.16 ; U3.18@695.05,1540.39 732.06,1540.39 v1(732.45,1540) ; U3.9@695.05,1682.13 725.32,1682.13 v1(727.45,1680) ; U3.33@845.44,1390 845.44,1427.99 v1(847.45,1430) ; v1(845.44,1812.99) U3.93@845.44,1848.27 ; U3.39@939.93,1390 939.93,1427.48 v1(942.45,1430) ; U3.85@971.43,1848.27 971.43,1811.02 v1(971.55,1810.9) ; v1(1117.45,1495) 1119.3,1493.15 U3.55@1153.32,1493.15
  Top Layer w8: U3.25@695.05,1430.16 717.61,1430.16 737.45,1450 v1(737.45,1455)
  Top Layer w9: U3.78@1081.66,1848.27 1081.66,1820.79 v1(1097.45,1805)
  Top Layer w15: v1(229.83,2408.34) 231.06,2407.11 L2.2@231.06,2229.97
  Bottom Layer w7: v1(847.45,1430) v1@851.58,1434.13
  Bottom Layer w15: v1(229.83,2408.34) Q15.1@281.11,2408.34 ; v1(845.44,1812.99) 845.68,1813.23 C92.1@879.13,1813.23
  other v1: -3.4,2121 205.31,2129.17 235.21,2130.78 263.51,2130.78
VIN: C27.1 C29.2 C33.2 C37.2 C39.2 C40.2 C41.1 C42.1 C43.2 D4.2 Q1.5 Q1.6 Q1.7 Q1.8 Q16.5 Q16.6 Q16.7 Q16.8 R32.1 R41.2 U4.4 | length 68.6
  Top Layer w22: v1(3615.9,1925) 3615.9,1958.13 R41.2@3616.63,1958.86 3616.63,1960.43 v1(3639.86,1983.66)
  other v1: 3496.99,1957.21 3490.47,1990.87 3486.05,2029.36 3970.89,2295.12 3736.21,2321.29 3784.81,2321.96 3826.12,2321.96 3867.83,2322.64 3970.89,2336.43 3736.21,2368.9 3784.81,2369.57 3826.12,2369.57 3867.83,2370.24 3970.22,2378.13 3724.15,2454.92 3761.64,2454.92 3724.17,2485.53 3761.63,2487.21 3724.15,2516.02 3761.61,2517.21 3724.18,2549.1 3761.61,2550.57 3724.15,2582.21 3761.61,2582.21 3724.2,2617.4 3761.59,2617.12 3820.11,2649.69 3853.37,2649.69 3889.83,2649.69 3921.76,2649.69 3958.01,2649.69 3989.83,2649.69
pads on no net: D11.2 D12.2 D13.2 D14.2 FID1.1 FID2.1 FID3.1 FID4.1 FID5.1 FID6.1 J2.0 J2.A8 J2.B8 J3.0 J3.A8 J3.B8 J10.4 J13.4 J20. J22.4 U9.1 U11.1

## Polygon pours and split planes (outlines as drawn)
5V_BRD on Top Layer "Full" (solid, remove dead copper, pour order 238): -25.58,1786.49 -25.58,1901.62 -6.76,1920.44 -6.76,1976.54 21.86,1976.54 21.86,1944.45 37.76,1928.55 37.76,1876.11 48.05,1865.82 48.05,1787.46 40.94,1780.36 -18.23,1780.36 -24.37,1786.49
3V3_BRD on Top Layer "Top Layer-3V3_BRD" (solid, pour order 290): 3134.8,1235 3143.08,1243.28 3143.08,1281.72 3129.8,1295 3015.48,1295 3009.3,1288.82 3009.3,1244.54 3018.84,1235
VBUS2 on Top Layer "Full" (solid, remove dead copper, pour order 210): 1076.05,74.87 1074.6,215.82 1081.13,228.76 1183.06,228.76 1199.02,244.73 1199.02,312.58 1183.06,330.69 1183.06,371.37 1163.71,392.31 1106.34,392.31 1068.49,430.15 1044.73,430.15 1022.47,452.41 1022.47,477.84 1093.94,477.84 1121.77,505.67 1202.76,505.67 1309,380.41 1309,72.71 1296.23,60.02 1086.42,60.02
VBUS1 on Top Layer "Full" (solid, remove dead copper, pour order 208): 784.74,74.87 835.44,74.87 848.91,86.77 848.91,213.84 835.44,226.85 763.64,226.85 756.44,238.69 756.44,322.95 763.64,330.36 795.41,331.31 796.32,332.36 881.38,430.67 905.14,430.67 927.4,452.93 927.4,478.36 855.94,478.36 839.63,494.66 791.44,494.66 658.04,494.66 639.65,478.36 639.65,86.77 650.56,74.87
VBUS_0 on Top Layer "Full" (solid, remove dead copper, pour order 289): 995.44,3183 991,3178.56 991,3120 958,3087 958,3058.2 965.2,3051 1089,3051 1097,3043 1097,2948 1104,2941 1132.58,2941 1139.75,2948.17 1139.75,3162.25 1119,3183
GND on Top Layer "Full" (solid, remove dead copper, pour order 281): 3680.22,2229.04 3698.52,2210.74 3698.52,2143.93 3689.64,2135.06 3689.64,2060.92 3694.15,2056.41 3778.58,2056.41 3802.53,2032.46 3802.53,1953.55 3850.76,1905.32 4564.47,1905.32 4594.15,1935 4594.15,2205 4574,2225.15 3753.14,2225.15 3689.64,2288.65 3689.64,2328.66 3677.94,2340.36 3540.82,2340.36 3527.61,2327.15 3527.61,2232.7 3531.27,2229.04
VBUS3 on Top Layer "Full" (solid, remove dead copper, pour order 279): 2997.17,198.77 3003.4,205 3003.4,349.05 2995.22,357.23 2844.51,357.23 2836.37,365.37 2836.37,506.18 2926.15,595.96 3051.8,595.96 3079.8,623.96 3079.8,650.96 2646.8,650.96 2633.8,637.96 2633.8,251.69 2642.7,242.79 2754.42,242.79 2798.44,198.77
GND on Top Layer "Full" (solid, remove dead copper, pour order 277): 3399.15,-35 3399.15,101.79 3355.4,145.54 3248.61,145.54 3232.62,161.53 3232.62,385 3237.62,390 3338.9,390 3349.15,400.25 3349.15,455 3339.15,465 3337.15,463 3266.8,463 3259.8,470 3259.8,480 3244.8,480 3244.8,470 3237.8,463 2925.85,463 2919.8,456.94 2919.8,381.35 3009.3,381.35 3039.8,350.85 3039.8,171.72 3025.44,157.36 2937.68,157.36 2917.3,136.99 2917.3,-58.15 2939.9,-80.75 3376.95,-80.75 3399.15,-58.54
GND on Top Layer "Full" (solid, remove dead copper, pour order 275): 639.65,-130 1304.65,-130 1317.65,-117 1317.65,32.37 1304.83,45.18 1077.27,45.18 1062.44,60.02 1062.44,236.07 1071.44,245.07 1174.31,245.07 1183.71,254.47 1183.71,302.48 1171.77,314.42 787.95,314.42 781.54,308.02 781.54,252.99 788.88,245.65 845.98,245.65 870.13,221.51 870.13,53.76 861.55,45.18 651.36,45.18 639.65,33.47
VBUS4 on Top Layer "Full" (solid, remove dead copper, pour order 271): 3254.8,190 3334.15,190 3464.15,60 3694.15,60 3744.15,110 3744.15,484.69 3577.88,650.96 3173.89,650.96 3173.89,625.24 3178.42,620.71 3188.07,611.07 3201.41,611.07 3294.15,518.33 3294.15,500 3299.15,495 3349.15,495 3364.15,480 3364.15,375 3349.15,360 3254.8,360
GND on Top Layer "Full" (solid, remove dead copper, pour order 267): -68.68,1974.13 -55.22,1987.59 25.96,1987.59 31.05,1982.49 30.88,1953.57 52.7,1931.75 52.7,1883.34 57.62,1878.42 81.83,1878.42 90.32,1886.91 90.32,1961.62 99.2,1970.5 160.11,1970.5 160.11,1987.46 156.59,1990.98 156.6,2017.99 160.11,2021.5 160.11,2093.57 156.08,2097.6 102.46,2097.6 90.32,2085.46 90.32,2054.32 85.39,2049.4 -64.97,2049.4 -92.87,2021.5 -163.31,2021.5 -170.85,2013.97 -170.85,1979.13 -165.85,1974.13
GND on Top Layer "Full" (solid, remove dead copper, pour order 265): -60.85,1855 -38.51,1877.34 -38.51,1911.03 -16.84,1932.89 -16.89,1976.54 -30.85,1976.54 -30.85,1948.49 -48.69,1932.89 -60.54,1932.89 -87.47,1905.96 -150.28,1905.96 -160.85,1895.39 -160.85,1764.34 -145.97,1749.46 -73.41,1749.46 -60.85,1762.02
NetF1_2 on Top Layer "Full" (solid, remove dead copper, pour order 261): 2911.87,2875.69 2995.49,2875.69 3151.7,3031.89 3370.5,3031.89 3370.5,3260 3369.02,3260 3359.02,3270 3049.09,3270 2883.84,3104.74 2883.84,2885.17 2892.18,2876.83
5V_BRD on Top Layer "Full" (solid, remove dead copper, pour order 259): 2814.15,1978.32 2824.18,1988.35 2825.26,2281.52 3049.15,2505.41 3049.15,2563.63 3036.37,2576.41 2991.6,2576.41 2964.29,2549.1 2559.92,2549.1 2543.28,2532.46 2543.28,2004.1 2543.28,1735 2552.46,1721.69 2665.84,1721.69 2674.15,1730 2679.15,1958.86 2695.92,1975.63
GND on Top Layer "Full" (solid, remove dead copper, pour order 257): 2574.15,2611.75 3152.89,2611.75 3184.15,2643.01 3184.15,2792.87 3215.84,2824.57 3646.16,2824.57 3670.33,2848.73 3670.33,2948.99 3661.91,2957.41 3577.73,2957.41 3565.32,2945 3565.32,2916.49 3541.32,2892.5 3434.52,2892.5 3357.68,2969.34 3145.99,2969.34 3025.38,2848.74 2890.34,2848.73 2834.15,2904.92 2834.15,2973.91 2798.06,3010 2577.65,3010 2562.06,2994.41 2562.06,2620.17 2568.84,2613.4
GND on Top Layer "Full" (solid, remove dead copper, pour order 255): 50.03,2363.12 62.13,2375.22 62.13,2735 229.83,2735 238.59,2743.75 238.59,2763.13 62.98,2763.13 -16.89,2843 -140.1,2843 -153.16,2829.94 -153.16,2369.83 -146.46,2363.12
3V3_BRD on Top Layer "Full" (solid, remove dead copper, pour order 253): 94.15,2782.69 250.36,2782.69 257.67,2790 256.83,2790.84 256.83,2853.56 293.35,2886.24 293.35,2953.1 286.72,2959.73 250.36,2959.73 223.05,2959.73 215.25,2951.93 215.25,2897.8 197.59,2880.15 197.59,2823.33 192.39,2818.13 94.36,2818.13
5V_BRD on Top Layer "Full" (solid, remove dead copper, pour order 251): 94.15,2685 174.02,2685 205.31,2653.71 205.31,2604.09 210.05,2599.35 256.83,2599.35 263.51,2606.03 263.51,2689.93 239.19,2714.25 93.73,2714.25 86.48,2707 86.48,2692.67
LVCORE on Top Layer "Full" (solid, remove dead copper, pour order 249): 78.13,2063.95 78.13,2093.57 126,2141.44 126,2312.37 46.96,2312.37 46.96,2107.44 27.27,2087.75 27.27,2063.95
no net on Top Layer "Full" (solid, remove dead copper, pour order 243): -13.26,2265
VCORE on Top Layer "Full" (solid, remove dead copper, pour order 241): -10.62,2067.41 -10.62,2102.46 -20.03,2111.87 -20.03,2201.71 -16.84,2204.9 19.7,2204.9 24.51,2200.1 24.51,2134.59 3.69,2113.78 3.69,2067.15 3.16,2066.63
VCORE on Top Layer "Full" (solid, remove dead copper, pour order 239): 127.03,1919.53 132.26,1924.76 187.97,1980.47 187.97,2151.38 172.22,2167.13 172.22,2308.52 182.52,2318.82 287.9,2318.82 299.27,2307.45 299.27,1811.02 290.29,1802.05 135.39,1802.05 127.03,1809.69 127.03,1833.55 127.03,1846.47
GND on Top Layer "Full" (solid, remove dead copper, pour order 236): 3269.02,2571.38 3277.01,2571.38 3419.24,2571.38 3424.07,2571.38 3428,2577.39 3428,2671.99 3414.56,2685.43 3266.91,2685.43 3262.24,2680.75 3262.24,2578.16
L5V on Top Layer "Full" (solid, remove dead copper, pour order 232): 3169.15,2304.73 3184.15,2319.73 3353.88,2319.73 3359.15,2325 3359.15,2355.72 3370.5,2367.07 3596.22,2367.07 3604.15,2375 3604.15,2425.83 3594.98,2435 3424.15,2435 3414.33,2444.82 3414.33,2538.33 3401.3,2551.35 3170.5,2551.35 2984.15,2365 2984.15,2093.08 3167.23,2093.08 3169.15,2095
VIN on Top Layer "Full" (solid, remove dead copper, pour order 230): 3459.15,2455.33 3689.64,2455.33 3714.15,2430.83 3714.15,2295 3739.15,2270 4324.15,2270 4343.7,2289.55 4343.7,2510.45 4329.15,2525 4149.15,2525 4134.15,2540 4134.15,2735 4119.15,2750 3706.65,2750 3670.33,2786.32 3581.66,2786.32 3242.41,2786.32 3229.15,2773.07 3229.15,2702.28 3236.43,2695 3424.87,2695 3444.02,2675.85 3444.02,2466.9 3454.15,2456.77
DC_IN on Top Layer "Full" (solid, remove dead copper, pour order 228): 3453.7,3090.95 3453.7,3029.28 3424.15,2999.73 3424.15,2934.87 3444.02,2915 3515.46,2915 3533.23,2932.77 3533.23,2969.08 3544.15,2980 3679.15,2980 3694.15,2965 3694.15,2820 3744.15,2770 4069.15,2770 4104.15,2805 4104.15,2915 4074.15,2945 3849.15,2945 3714.15,3080 3714.15,3250 3694.15,3270 3464.15,3270 3454.15,3260
VIN on Top Layer "Full" (solid, remove dead copper, pour order 226): 3528.17,1950 3528.17,2042.01 3522.4,2047.77 3496.28,2047.77 3483.23,2060.82 3483.23,2093.08 3464.62,2093.08 3464.62,2009.06 3473.68,2000 3473.68,1946.47 3476.42,1943.73 3520.46,1943.73
5V_BRD on Top Layer "Full" (solid, remove dead copper, pour order 206): 895.94,330.36 913.08,347.5 1034.05,347.5 1053.22,328.33 1162.52,328.33 1166.9,332.71 1166.9,371.39 1157.43,380.86 1099.44,380.86 1062.44,417.86 1042.99,417.86 1015.39,445.45 933.89,445.45 906.52,418.08 887.66,418.08 835.44,365.86 835.44,332.36 837.44,330.36
5V_BRD on Top Layer "full" (solid, remove dead copper, pour order 150): 3054.8,509.96 3129.8,509.96 3259.8,509.96 3264.8,514.96 3264.8,529.96 3244.8,549.96 3209.8,584.96 3184.8,584.96 3174.8,594.96 3174.8,607.17 3174.09,607.88 3085.51,607.88 3063.86,586.22 2936.91,586.22 2914.8,564.11 2914.8,514.96 2919.8,509.96
VBUS2 on Bottom Layer "Full" (solid, remove dead copper, pour order 214): 1225.67,163.51 1479.7,163.51 1487.65,171.46 1487.65,327.51 1498.06,337.92 1588.96,337.92 1598.37,328.5 1598.38,305.65 1572.65,279.92 1572.65,193.68 1567.75,188.78 1567.75,161.13 1577.59,151.29 1687.88,151.29 1702.65,166.06 1702.65,319.04 1599.46,422.23 1436.27,422.24 1352.65,505.86 1242.65,505.86 1208.28,463.76 1208.28,180.9
GND on Bottom Layer "Full" (solid, remove dead copper, pour order 287): -170.85,1728.25 81.4,1728.25 102.06,1748.91 102.06,2055.74 91.02,2066.78 -167.51,2066.78 -170.85,2063.44
DC_IN on Bottom Layer "Full" (solid, remove dead copper, pour order 285): 4069.94,2490 4095.96,2516.02 4135.09,2516.02 4141.65,2522.58 4141.65,2867.5 4094.15,2915 3852.56,2915 3836.19,2898.63 3836.19,2817.96 3849.15,2805 3969.89,2805 3986.07,2788.82 3986.07,2750.83 3964.15,2728.91 3964.15,2685.21 3970.89,2678.47 4013.8,2678.47 4019.15,2673.11 4019.15,2622.4 4014.15,2617.4 4014.15,2490
VBUS3 on Bottom Layer "Full" (solid, remove dead copper, pour order 273): 2244.15,276.47 2367.06,276.47 2449.15,276.47 2644.15,276.47 2656.48,288.8 2656.48,529.65 2634.48,551.65 2633.8,639.71 2644.15,650.96 2674.15,650.96 2857.9,650.96 2869.15,639.71 2869.15,538.96 2869.15,316.98 2869.15,93.98 2869.15,-15 2849.15,-45 2285.19,-45 2231.62,2.18 2231.62,219.31 2231.62,263.94
VCORE on Bottom Layer "Full" (solid, remove dead copper, pour order 245): 1123.28,1392.71 1141.47,1410.9 1141.47,1515.79 1136.18,1523.03 1104.23,1523.03 1060.8,1470.96 965.12,1472.14 768.25,1470.96 747.56,1472.14 745.26,1663.84 745.26,1776.61 761.95,1793.3 782.31,1793.3 869.95,1793.3 994.39,1793.3 998.97,1797.89 1071.1,1797.89 1079.38,1790.55 1110.04,1790.55 1117.38,1797.89 1117.38,1840.27 1110.04,1847.6 679.97,1849.5 636.76,1806.3 293.89,1806.3 272.51,1827.68 272.51,2080.41 293.89,2094.59 293.89,2158.84 286.34,2167.71 -19.89,2167.71 -26.17,2161.44 -26.17,2116.17 -19.66,2106.91 96.8,2105.91 117.98,2088.42 117.98,2080.41 117.98,1658.34 190.25,1586.07 633.63,1586.07 650.56,1569.14 650.56,1411.97 669.82,1392.71
VIN on Bottom Layer "Full" (solid, remove dead copper, pour order 234): 3995.02,2288.65 3995.02,2419.29 3995.02,2625.87 4006.83,2637.68 4006.83,2659.56 3996.82,2669.57 3932.65,2669.57 3925.56,2676.66 3925.56,2731.2 3921.76,2735 3879.34,2735 3864.15,2750.2 3864.15,2785.47 3857.45,2792.17 3822.26,2792.17 3815.33,2785.24 3815.33,2678.47 3796.67,2659.8 3675.64,2659.8 3672.4,2656.57 3672.4,2416.75 3672.4,2117.09 3605.31,2050 3474.15,2050 3464.15,2042.63 3464.15,1900 3469.94,1894.21 3768.45,1893.64 3796.67,1921.85 3796.67,2218.91 3854.03,2270 3974.15,2270
no net on Bottom Layer "Full" (solid, remove dead copper, pour order 222): 348.52,343.44
VBUS1 on Bottom Layer "Full" (solid, remove dead copper, pour order 220): 294.93,156.61 294.93,384.18 335.2,424.45 702.15,424.45 756.44,370.16 756.44,272.49 726.7,242.75 598.58,242.75 534.52,306.81 442.57,306.81 432.19,296.43 432.19,262.63 442.34,252.49 442.34,179.16 414.79,151.61 301.64,151.61 296.65,156.61
GND on Bottom Layer "SPOKES" (solid, remove dead copper, pour order 198): 784.46,1473.07 786.39,1475 1062.45,1475 1062.45,1752.99 1060.44,1755 787.45,1755
no net on Top Assy TOP (M11)/Assy BOT (M10) (solid): 3018.84,1230.3
5V_BRD on Layer 3 (split plane): 4599.05,-154.9 -160.75,-154.9 -160.75,3304.9 4599.05,3304.9
3V3_BRD on Layer 3 (split plane): 161 vertices, not listed, extent -27.11,17.81 3253.6,3069.45
EARTH_P1 on Layer 2 (split plane): 580.07,-162.93 153.23,-162.93 153.23,-54.08 580.07,-54.08
EARTH_P2 on Layer 2 (split plane): 1854.6,-162.93 1427.79,-162.93 1427.79,-54.08 1854.6,-54.08
GND on Layer 2 (split plane): 4607.08,-162.93 1862.76,-162.93 1862.76,-50 1862.45,-48.44 1861.57,-47.12 1860.24,-46.23 1858.68,-45.92 1425.5,-45.92 1425.27,-45.76 1423.71,-45.45 1422.15,-45.76 1420.82,-46.65 1419.94,-47.97 1419.63,-49.53 1419.63,-162.93 588.23,-162.93 588.23,-50 587.92,-48.44 587.03,-47.12 585.71,-46.23 584.15,-45.92 149.15,-45.92 147.59,-46.23 146.27,-47.12 145.38,-48.44 145.07,-50 145.07,-162.93 -168.78,-162.93 -168.78,3312.93 4607.08,3312.93

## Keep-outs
Keep-Out Layer:
  text ".Layer_Name" at 11420.01,-4182.53 h59.06

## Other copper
Top Layer:
  region: 1153.32,1556.14
  region: 1160.4,1551.21
  text ".Layer_Name" at 1187.6,-376 h110
  text ".Layer_Name" at 11420.01,-4182.53 h59.06
  text ".ProjectRevisionART" at 12774.96,-4185.53 h59.06
Bottom Layer:
  text "UNG-8243-A0" at 4539.15,1445 h120 r90
  text ".Layer_Name" at 1171.6,-378 h110
  text ".Layer_Name" at 11420.01,-4182.53 h59.06
  text ".ProjectRevisionART" at 12774.96,-4185.53 h59.06
  text ".ProjectRevisionART" at 12774.96,-4185.53 h59.06
  text ".ProjectRevisionART" at 12774.96,-4185.53 h59.06
Layer 2 (plane layer: these items are gaps in the copper):
  lines w8: 149.15,-175 149.15,-50 584.15,-50 584.15,-175 ; 1423.71,-175 1423.71,-49.53 1424.18,-50 1858.68,-50 1858.68,-175
  text ".Layer_Name" at 1179.6,-365 h110
  text ".Layer_Name" at 11420.01,-4182.53 h59.06
Layer 3 (plane layer: these items are gaps in the copper):
  lines w11: 86.48,2465.02 86.48,2460.99 ; 136.86,2250 136.86,2261.64 ; 1224.15,588.04 1224.15,617.32 ; 1224.15,597.47 1224.15,375.97 1199.15,350.97 1199.15,32.47 1219.36,12.26 2896.41,12.26 2909.15,25 2909.15,600 2924.15,615 3241.59,615 3259.15,632.56 3259.15,715 3239.15,735 3219.15,755 3219.15,815 ; 1224.15,602.68 1224.15,617.32 ; 1493.88,664.29 1484.93,664.29 ; 1795.67,691.52 1795.7,691.52 ; 3219.15,787.77 3219.15,1460.16 3192.31,1487 2576.03,1487 2525,1538.03 2525,2501.1 2525,3056 2506.08,3074.92 2505.35,3074.92 2505.27,3075 1656.1,3075 1626.1,3045 1513.84,3045 1486.45,3072.39 182.39,3072.39 142.4,3032.4 142.4,2847.74 155.14,2835 245.46,2835 425,2835 443.5,2816.5 443.5,2805.98 432.51,2795 375,2795 275.09,2695.09 275.09,2551.3 257.91,2534.12 109.89,2534.12 86.48,2510.71 86.48,2460.99 ; 86.48,2460.99 -32.66,2341.85 -32.66,2306.81 -22.29,2296.44 102.71,2296.44 102.06,2296.44 136.86,2261.64 ; 136.86,2261.64 136.86,1856.67 19.7,1739.52 19.7,1662.99 59.15,1623.55 59.15,893.57 107.72,845 117.72,835 271.63,835 346.84,910.21 513.66,910.21 610.21,813.66 1178.55,813.66 1263.2,898.31 1777.31,898.31 1795.7,879.92 1795.7,691.52 ; 1224.15,617.32 1259.83,653 1271.12,664.29 1419.18,664.29 1484.93,664.29 ; 1484.93,664.29 1768.48,664.29 1795.7,691.52
  text ".Layer_Name" at 1176.6,-370 h110
  text ".Layer_Name" at 11420,-4177.5 h59.06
